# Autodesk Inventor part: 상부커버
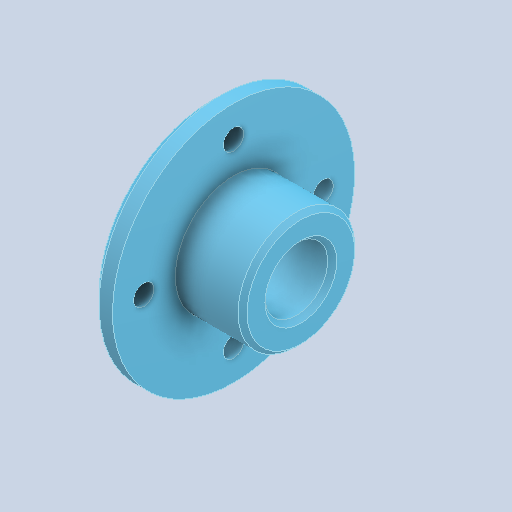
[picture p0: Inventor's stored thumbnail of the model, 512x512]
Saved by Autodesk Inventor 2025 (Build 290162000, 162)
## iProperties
Created: 2024-07
Part Number: 상부커버
Material: 알루미늄 6061
Document SubType Name: Modeling
Designer: myung
Density: 2.71 g/cm^3
Appearance: 기본값
Author: jhkim
Sending System: Autodesk Inventor 2025
Preprocessor: ST-DEVELOPER v20
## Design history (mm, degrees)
feature "솔리드1"
node "솔리드2"
